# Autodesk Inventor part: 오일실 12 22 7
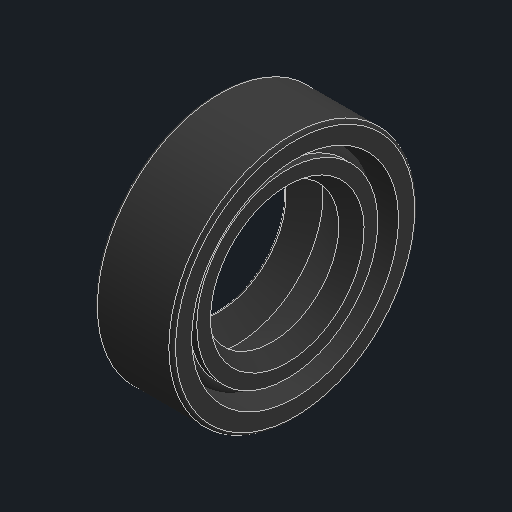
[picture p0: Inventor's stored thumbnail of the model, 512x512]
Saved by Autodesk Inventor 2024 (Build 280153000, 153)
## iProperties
Created: 2024-05
Part Number: 오일실 12 22 7
Material: 고무
Description: 오일-실
Document SubType Name: Modeling
Designer: kh_501
Density: 0.93 g/cm^3
Appearance: 기본값
Sending System: Autodesk Inventor 2025
Preprocessor: ST-DEVELOPER v20
Author: jhkim
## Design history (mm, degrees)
feature "Solid1"
node "솔리드1"
